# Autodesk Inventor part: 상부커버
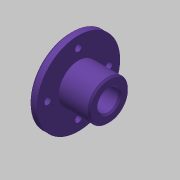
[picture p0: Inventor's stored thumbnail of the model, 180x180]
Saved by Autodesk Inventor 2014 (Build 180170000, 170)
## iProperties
Created: 2015-09
Part Number: 상부커버
Material: 알루미늄 6061
Document SubType Name: Modeling
Designer: mduedu
Density: 1 g/cm^3
Appearance: 보라색
Author: mduedu
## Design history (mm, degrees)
sketch "스케치1"
  geometry: L1 (-12.5, 0)-(12.5, 0); L2 (-12.5, 0)-(-12.5, 27); L3 (-12.5, 27)-(-7.5, 27); L4 (-7.5, 27)-(-7.5, 13); L5 (-7.5, 13)-(12.5, 13); L6 (12.5, 13)-(12.5, 0); 2 further points
  constraints: 12 end point, 2 parallel, 2 perpendicular, 1 coincident, 1 horizontal, 1 midpoint, 1 vertical
  dimensions: "d0" = 25 distance of L1.start L1.end; "d2" = 5 distance of L2.end L3.end; "d3" = 26 diameter of L5 L1; "d4" = 54 diameter of L3 L1
revolve "회전1" sketch "스케치1" stored, may be unused: angle "d5" = 90 deg
hole "구멍1" diameter "d8" = 14; stored, may be unused: countersink angle "d12" = 90 deg, drill point angle "d14" = 118 deg; dims "d6" = 10, "d7" = 10, "d9" = 6, "d10" = 4, "d11" = 2, "d13" = 8
chamfer "모따기1" distance "d15" = 1; stored, may be unused: second distance "d16" = 2, angle "d17" = 45 deg
chamfer "모따기2" distance "d18" = 1; stored, may be unused: second distance "d19" = 2, angle "d20" = 45 deg
sketch "스케치2" dims "d21" = 40
  geometry: 6 further points
  constraints: 2 vertical alignment, 1 coincident, 7 other
  dimensions: "d25" = 360 deg dimension on point (0, 0) point (0, 20) (derived)
sketch "스케치3"
  geometry: 4 further points
hole "구멍2" sketch "스케치3" at (0, 20), (-20, 0), (20, 0), (0, -20) diameter "d27" = 4.5; stored, may be unused: countersink angle "d31" = 90 deg, drill point angle "d33" = 0 deg; dims "d28" = 6, "d29" = 4, "d30" = 2, "d32" = 8
chamfer "모따기3" distance "d34" = 1; stored, may be unused: second distance "d35" = 2, angle "d36" = 45 deg
node "솔리드1"
